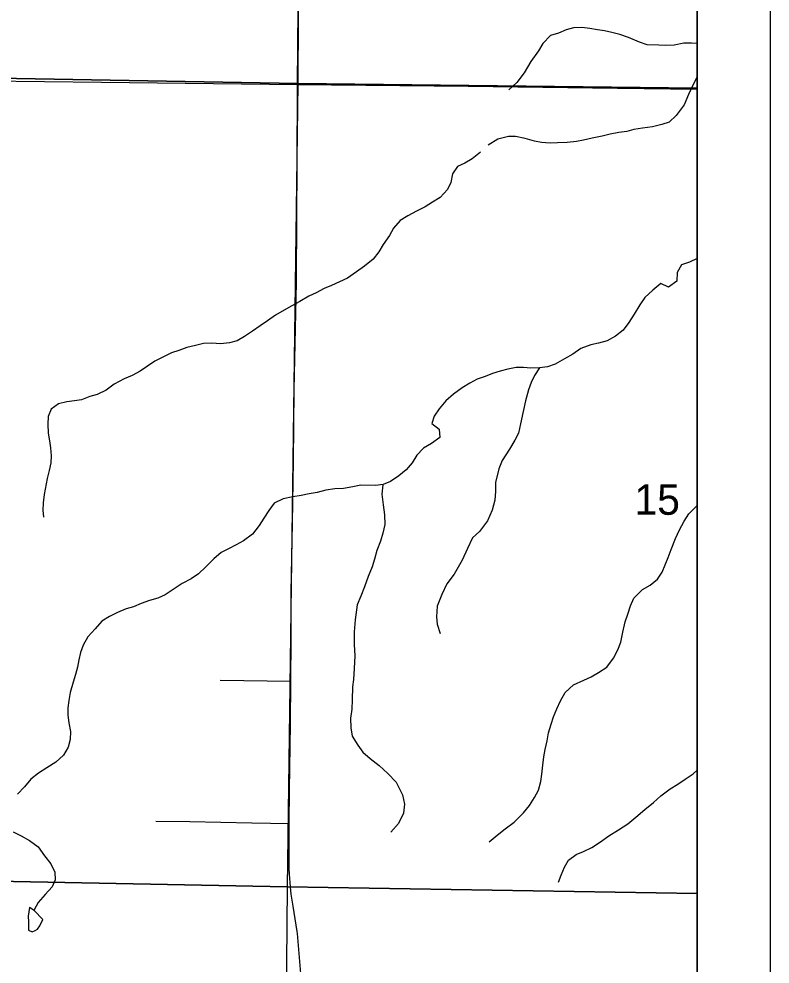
# Model space of a CAD drawing. Extents: x -8.8 to 41.4, y 0 to 34.6.
# Drawn here: x -2.803 to -1.774, y 15.304 to 16.599 of the extents above; entities that cross this region are included whole.
import ezdxf

# ---------------------------------------------------------------- set-up
doc = ezdxf.new("R2010")
doc.units = 0
for name, color, linetype in [('GM_X_Corporation', 7, 'Continuous'), ('GM_X_County_Road', 7, 'Continuous'), ('GM_X_Minor_River', 7, 'Continuous'), ('GM_X_Township_Road', 7, 'Continuous'), ('GM_X_Township_Text', 7, 'Continuous'), ('SH_Border', 7, 'Continuous')]:
    doc.layers.add(name, color=color, linetype=linetype)

msp = doc.modelspace()

# ---------------------------------------------------------------- linework, layer by layer
at = {"layer": 'GM_X_Corporation'}
msp.add_lwpolyline([(-5.4008, 18.6369), (-5.4129, 17.3836), (-5.4212, 16.5483), (-5.4282, 16.3507), (-5.435, 15.3164), (-5.4368, 15.0446), (-5.4404, 14.5882), (-5.4429, 14.2618), (-5.4432, 14.2265), (-5.4442, 14.1), (-1.8743, 14.1), (-1.8743, 18.5906)], dxfattribs=at)
for points in [[(-2.4162, 17.5144), (-2.421, 16.5107), (-3.4233, 16.5283), (-3.4102, 17.5315)], [(-1.8743, 16.504), (-1.8743, 17.5082), (-2.4162, 17.5144), (-2.421, 16.5107)], [(-3.4233, 16.5283), (-2.421, 16.5107), (-2.4357, 15.4097), (-3.4436, 15.4293)], [(-1.8743, 15.4006), (-1.8743, 16.504), (-2.421, 16.5107), (-2.4357, 15.4097)], [(-3.4436, 15.4293), (-2.4357, 15.4097), (-2.4445, 14.411), (-3.4507, 14.4245)], [(-1.8743, 14.4042), (-1.8743, 15.4006), (-2.4357, 15.4097), (-2.4445, 14.411)]]:
    msp.add_lwpolyline(points, close=True, dxfattribs=at)
at = {"layer": 'GM_X_County_Road'}
msp.add_lwpolyline([(-2.9247, 16.5151), (-2.6903, 16.5124), (-2.4218, 16.5093), (-2.1878, 16.5068), (-1.9834, 16.5044), (-1.8743, 16.5027)], dxfattribs=at)
at = {"layer": 'GM_X_Minor_River'}
for points in [[(-1.8743, 16.5653), (-1.8818, 16.566), (-1.8925, 16.5659), (-1.9058, 16.5632), (-1.9172, 16.5627), (-1.9267, 16.563), (-1.9426, 16.5637), (-1.9531, 16.567), (-1.9681, 16.5738), (-1.9802, 16.5779), (-1.9911, 16.5805), (-2.0009, 16.5826), (-2.0107, 16.584), (-2.0213, 16.5861), (-2.0323, 16.5875), (-2.0437, 16.5867), (-2.0536, 16.5839), (-2.0639, 16.5796), (-2.075, 16.5765), (-2.0855, 16.5653), (-2.0915, 16.5552), (-2.1021, 16.5407), (-2.1112, 16.5254), (-2.121, 16.512), (-2.1322, 16.502)], [(-1.8743, 16.5199), (-1.8802, 16.5083), (-1.8859, 16.4956), (-1.8919, 16.4813), (-1.9029, 16.4668), (-1.9126, 16.4576), (-1.9225, 16.4544), (-1.9355, 16.4513), (-1.9492, 16.4494), (-1.961, 16.4474), (-1.9706, 16.4449), (-1.9816, 16.4433), (-1.9934, 16.441), (-2.0041, 16.4382), (-2.0182, 16.4355), (-2.0297, 16.4331), (-2.0396, 16.4311), (-2.0521, 16.4299), (-2.0654, 16.4291), (-2.0757, 16.4289), (-2.0874, 16.4296), (-2.0972, 16.4317), (-2.11, 16.4351), (-2.1232, 16.4381), (-2.1327, 16.4379), (-2.1472, 16.4345), (-2.1603, 16.4261)], [(-2.1711, 16.4163), (-2.1824, 16.4075), (-2.1924, 16.4013), (-2.2024, 16.3966), (-2.2092, 16.3869), (-2.2118, 16.3748), (-2.2162, 16.3651), (-2.2264, 16.3544), (-2.2365, 16.3478), (-2.2469, 16.3416), (-2.2588, 16.3355), (-2.2704, 16.3294), (-2.2808, 16.3228), (-2.2902, 16.3124), (-2.2958, 16.3023), (-2.3041, 16.29), (-2.3101, 16.28), (-2.318, 16.2699), (-2.33, 16.26), (-2.3408, 16.2523), (-2.3532, 16.2439), (-2.364, 16.2389), (-2.3751, 16.2335), (-2.3851, 16.2296), (-2.3959, 16.2239), (-2.4059, 16.2192), (-2.4186, 16.2116), (-2.4294, 16.2058), (-2.4398, 16.2), (-2.4518, 16.1931), (-2.4627, 16.1851), (-2.4727, 16.1785), (-2.4832, 16.1712), (-2.4944, 16.1639), (-2.5044, 16.1581), (-2.5147, 16.155), (-2.5269, 16.1538), (-2.539, 16.1545), (-2.5504, 16.1541), (-2.5615, 16.1514), (-2.573, 16.1487), (-2.5841, 16.1448), (-2.594, 16.1413), (-2.606, 16.1355), (-2.6171, 16.1298), (-2.6272, 16.1232), (-2.6372, 16.1163), (-2.648, 16.1105), (-2.6592, 16.1059), (-2.6727, 16.0983), (-2.6839, 16.0902), (-2.6962, 16.0845), (-2.7061, 16.0817), (-2.7173, 16.0771), (-2.7272, 16.0755), (-2.7378, 16.0743), (-2.7489, 16.0715), (-2.759, 16.0642), (-2.7631, 16.0541), (-2.7638, 16.0435), (-2.763, 16.0313), (-2.7614, 16.021), (-2.7601, 16.0111), (-2.7589, 16.0004), (-2.7596, 15.9905), (-2.7618, 15.9803), (-2.7644, 15.969), (-2.7688, 15.9471), (-2.7699, 15.9357), (-2.7705, 15.9259), (-2.7697, 15.916)], [(-1.8743, 16.2708), (-1.8848, 16.2657), (-1.8955, 16.2622), (-1.9015, 16.2514), (-1.9022, 16.2396), (-1.9135, 16.2315), (-1.9239, 16.2364), (-1.9348, 16.2272), (-1.9457, 16.2173), (-1.9528, 16.2072), (-1.9604, 16.1945), (-1.9676, 16.1829), (-1.9755, 16.1725), (-1.9859, 16.1641), (-1.9975, 16.1579), (-2.0093, 16.1548), (-2.02, 16.1525), (-2.0335, 16.1472), (-2.0443, 16.1395), (-2.0559, 16.1333), (-2.0686, 16.1261), (-2.0793, 16.1222), (-2.09, 16.121), (-2.1021, 16.1206), (-2.112, 16.1212), (-2.1222, 16.1212), (-2.1333, 16.1192), (-2.144, 16.1164), (-2.1547, 16.1133), (-2.1647, 16.109), (-2.1754, 16.1052), (-2.1858, 16.0998), (-2.1959, 16.0936), (-2.2079, 16.0848), (-2.2184, 16.0756), (-2.2274, 16.0645), (-2.2345, 16.0548), (-2.2375, 16.0446), (-2.2274, 16.0367), (-2.2266, 16.0253), (-2.2382, 16.0173), (-2.2491, 16.0107), (-2.2581, 16.0011), (-2.2644, 15.9906), (-2.2727, 15.981), (-2.2828, 15.9729), (-2.2944, 15.9653), (-2.3043, 15.961), (-2.3146, 15.9594), (-2.3351, 15.96), (-2.3458, 15.9576), (-2.3584, 15.9557), (-2.3705, 15.9552), (-2.3827, 15.9533), (-2.3946, 15.9502), (-2.4056, 15.9483), (-2.4167, 15.9459), (-2.4281, 15.9443), (-2.4411, 15.9413), (-2.4534, 15.9355), (-2.4609, 15.9255), (-2.4677, 15.9147), (-2.474, 15.9046), (-2.4831, 15.8927), (-2.4955, 15.8839), (-2.5055, 15.8781), (-2.5163, 15.8727), (-2.5263, 15.8677), (-2.5364, 15.8592), (-2.5473, 15.8481), (-2.5571, 15.8385), (-2.5672, 15.8316), (-2.5795, 15.8251), (-2.5907, 15.8178), (-2.6031, 15.8098), (-2.6131, 15.8051), (-2.6245, 15.802), (-2.636, 15.7978), (-2.6464, 15.7935), (-2.6564, 15.7904), (-2.6683, 15.7854), (-2.679, 15.78), (-2.6895, 15.7735), (-2.6989, 15.7631), (-2.709, 15.7524)], [(-2.09, 16.121), (-2.0969, 16.1105), (-2.1014, 16.1007), (-2.1051, 16.0906), (-2.1093, 16.0755), (-2.1124, 16.0612), (-2.1164, 16.0442), (-2.119, 16.0314), (-2.1239, 16.0216), (-2.1314, 16.0093), (-2.1414, 15.9941), (-2.1459, 15.9824), (-2.1503, 15.9639), (-2.1502, 15.9514), (-2.1514, 15.9397), (-2.1552, 15.9257), (-2.1613, 15.9111), (-2.1724, 15.8966), (-2.1821, 15.8878), (-2.1886, 15.8732), (-2.1963, 15.8575), (-2.2071, 15.838), (-2.217, 15.825), (-2.2239, 15.8104), (-2.2301, 15.7943), (-2.2313, 15.7795), (-2.2301, 15.7696), (-2.2263, 15.757)], [(-2.3043, 15.961), (-2.3048, 15.9606), (-2.3063, 15.9477), (-2.3045, 15.9332), (-2.3026, 15.9195), (-2.3022, 15.9062), (-2.3049, 15.8945), (-2.3079, 15.8832), (-2.3128, 15.8704), (-2.3162, 15.8588), (-2.3195, 15.8482), (-2.3249, 15.8347), (-2.3298, 15.8208), (-2.3348, 15.8081), (-2.3397, 15.796), (-2.3426, 15.7756), (-2.3438, 15.759), (-2.344, 15.7419), (-2.3433, 15.7263), (-2.3438, 15.7088), (-2.3447, 15.6937), (-2.3461, 15.6838), (-2.3466, 15.666), (-2.3474, 15.6531), (-2.3489, 15.6406), (-2.3485, 15.6277), (-2.3466, 15.6159), (-2.339, 15.6039), (-2.3321, 15.5942), (-2.3221, 15.5855), (-2.3098, 15.576), (-2.298, 15.565), (-2.2866, 15.5529), (-2.2777, 15.5356), (-2.275, 15.523), (-2.2765, 15.5105), (-2.2834, 15.4963), (-2.2936, 15.4844)], [(-2.1589, 15.4713), (-2.148, 15.4805), (-2.1371, 15.4893), (-2.1247, 15.4984), (-2.1119, 15.511), (-2.104, 15.521), (-2.0968, 15.5318), (-2.0916, 15.542), (-2.0882, 15.554), (-2.0868, 15.5639), (-2.0857, 15.5764), (-2.0843, 15.5877), (-2.0824, 15.5979), (-2.0798, 15.6096), (-2.078, 15.6206), (-2.0742, 15.6327), (-2.0709, 15.6428), (-2.0664, 15.6537), (-2.0616, 15.6646), (-2.0548, 15.6758), (-2.0435, 15.6865), (-2.0293, 15.693), (-2.0193, 15.6976), (-2.0093, 15.7034), (-1.998, 15.7107), (-1.9886, 15.723), (-1.9829, 15.7346), (-1.9789, 15.7451), (-1.9758, 15.7587), (-1.9728, 15.7727), (-1.969, 15.7832), (-1.9657, 15.7949), (-1.9608, 15.805), (-1.9491, 15.8169), (-1.9387, 15.823), (-1.9286, 15.8311), (-1.9223, 15.8408), (-1.9178, 15.8509), (-1.9141, 15.8611), (-1.91, 15.872), (-1.9039, 15.887), (-1.8986, 15.899), (-1.8918, 15.9106), (-1.8855, 15.9207), (-1.8743, 15.9324)], [(-2.709, 15.7524), (-2.7154, 15.7408), (-2.7188, 15.7306), (-2.7213, 15.7208), (-2.7231, 15.7106), (-2.7257, 15.7008), (-2.729, 15.6899), (-2.7328, 15.6759), (-2.7347, 15.6649), (-2.7361, 15.6547), (-2.736, 15.6448), (-2.7348, 15.6345), (-2.7325, 15.6223), (-2.7331, 15.6113), (-2.7357, 15.6011), (-2.7421, 15.5899), (-2.7526, 15.5803), (-2.765, 15.5727), (-2.7762, 15.5654), (-2.7867, 15.557), (-2.7957, 15.5466), (-2.8051, 15.5366)], [(-2.0641, 15.4158), (-2.0604, 15.4256), (-2.0559, 15.4365), (-2.0503, 15.4462), (-2.0399, 15.4539), (-2.0299, 15.4581), (-2.0183, 15.4635), (-2.0064, 15.4712), (-1.9951, 15.4796), (-1.982, 15.4879), (-1.9692, 15.4959), (-1.9583, 15.5051), (-1.9459, 15.5158), (-1.9339, 15.5254), (-1.9238, 15.5342), (-1.9113, 15.5437), (-1.9005, 15.5503), (-1.8905, 15.5572), (-1.8796, 15.5645), (-1.8743, 15.5694)], [(-2.8111, 15.4851), (-2.8003, 15.4795), (-2.7887, 15.473), (-2.7768, 15.4644), (-2.768, 15.4523), (-2.7596, 15.4411), (-2.7542, 15.4299), (-2.7534, 15.4192), (-2.7578, 15.4095), (-2.7673, 15.3991), (-2.7767, 15.388), (-2.7823, 15.3779), (-2.7825, 15.377)], [(-2.7825, 15.377), (-2.7889, 15.3811), (-2.7907, 15.3694), (-2.7902, 15.3614), (-2.79, 15.3549), (-2.7902, 15.3504), (-2.7853, 15.3479), (-2.7811, 15.3497)], [(-2.7811, 15.3497), (-2.7776, 15.3515), (-2.7744, 15.356), (-2.7704, 15.365), (-2.7825, 15.377)]]:
    msp.add_lwpolyline(points, dxfattribs=at)
at = {"layer": 'GM_X_Township_Road'}
msp.add_line((-2.5277, 15.6927), (-2.4306, 15.6915), dxfattribs=at)
for points in [[(-2.4218, 16.5093), (-2.4201, 16.6656), (-2.4191, 16.7948), (-2.4182, 16.904), (-2.4181, 16.9674), (-2.418, 17.014), (-2.4176, 17.1891), (-2.4168, 17.2928), (-2.4171, 17.3417)], [(-2.4171, 15.2908), (-2.4218, 15.3458), (-2.4222, 15.3483), (-2.4276, 15.3833), (-2.429, 15.3912), (-2.4301, 15.3994), (-2.4312, 15.4098), (-2.4327, 15.4271), (-2.433, 15.4345), (-2.4329, 15.4532), (-2.4329, 15.4964), (-2.4326, 15.5421), (-2.4312, 15.6328), (-2.4306, 15.6915), (-2.4303, 15.7487), (-2.4301, 15.8133), (-2.4284, 15.908), (-2.4269, 15.9932), (-2.426, 16.0906), (-2.4229, 16.2384), (-2.4224, 16.3291), (-2.4221, 16.3968), (-2.4218, 16.5093)], [(-2.6157, 15.4996), (-2.5692, 15.4991), (-2.4841, 15.4974), (-2.4329, 15.4964)]]:
    msp.add_lwpolyline(points, dxfattribs=at)
at = {"layer": 'SH_Border'}
for p, q in [((-1.7743, 21), (-1.7743, 14)), ((-1.8743, 20.9), (-1.8743, 14.1))]:
    msp.add_line(p, q, dxfattribs=at)

# ---------------------------------------------------------------- texts
at = {"layer": 'GM_X_Township_Text'}
msp.add_text('15', height=0.04186, rotation=0, dxfattribs=at).set_placement((-1.9601, 15.9195))

doc.saveas('drawing.dxf')
